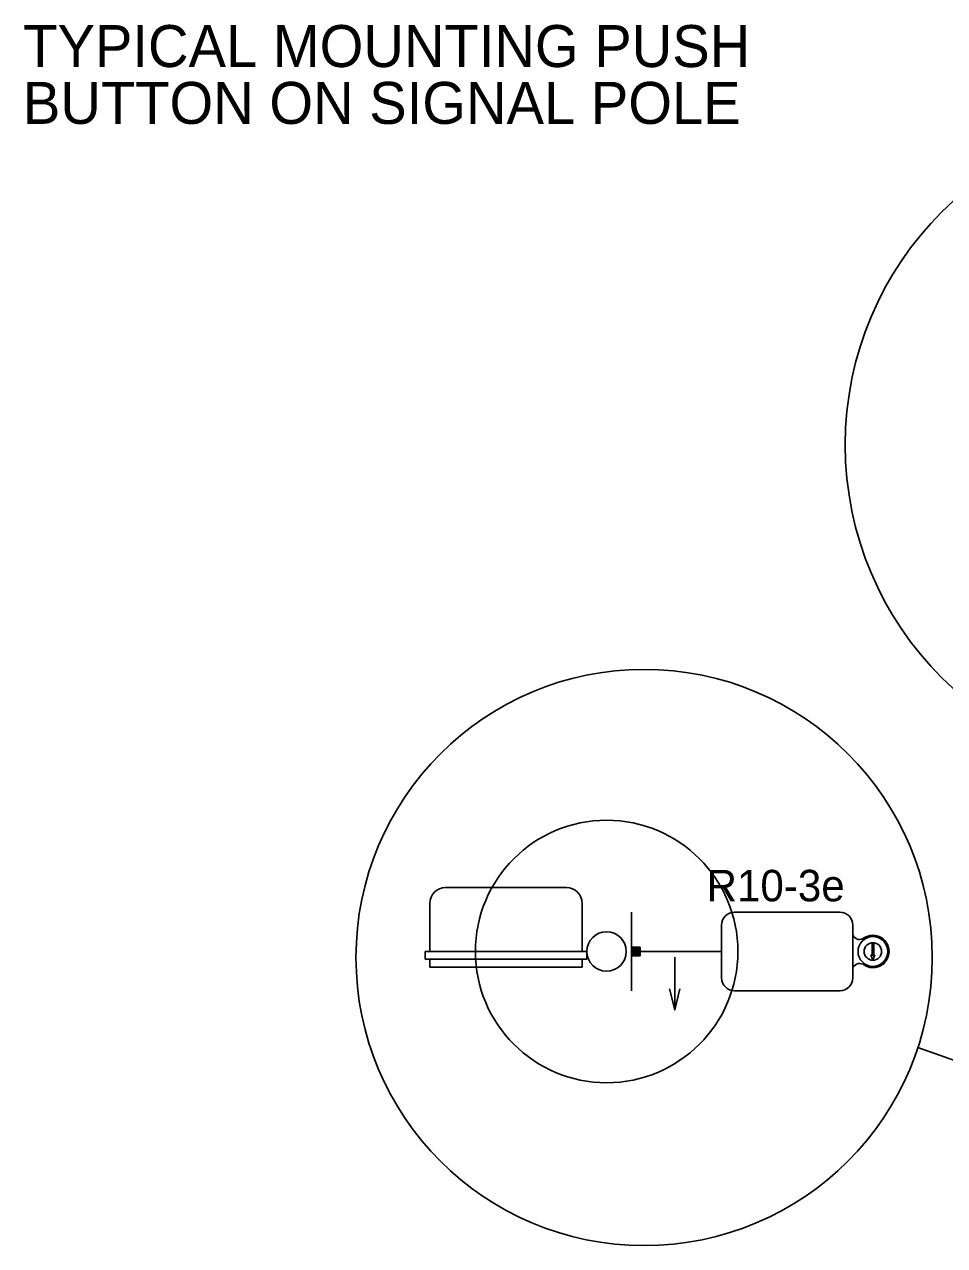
# Model space of a CAD drawing. Extents: x 1695551 to 1695718, y 544410 to 544516.
# Drawn here: x 1695672.78 to 1695694.69, y 544427.73 to 544456.81 of the extents above; entities that cross this region are included whole.
import ezdxf

# ---------------------------------------------------------------- set-up
doc = ezdxf.new("R2010")
doc.units = 0
doc.layers.add('R_Draft', color=7, linetype='Continuous')
doc.layers.add('T_Drafting', color=7, linetype='Continuous')

msp = doc.modelspace()

# ---------------------------------------------------------------- linework, layer by layer
at = {"layer": 'T_Drafting'}
for p, q in [((1695682.808, 544436.257), (1695685.683, 544436.257)), ((1695682.433, 544434.736), (1695682.433, 544435.882)), ((1695686.058, 544434.736), (1695686.058, 544435.882)), ((1695687.235, 544435.674), (1695687.235, 544433.799)), ((1695692.193, 544435.674), (1695689.689, 544435.674)), ((1695689.377, 544435.361), (1695689.377, 544434.111)), ((1695692.506, 544434.111), (1695692.506, 544435.361)), ((1695687.443, 544434.84), (1695687.235, 544434.84)), ((1695687.235, 544434.633), (1695687.442, 544434.84)), ((1695687.235, 544434.636), (1695687.439, 544434.84)), ((1695687.235, 544434.64), (1695687.435, 544434.84)), ((1695687.235, 544434.643), (1695687.432, 544434.84)), ((1695687.235, 544434.647), (1695687.428, 544434.84)), ((1695687.235, 544434.651), (1695687.425, 544434.84)), ((1695687.235, 544434.654), (1695687.421, 544434.84)), ((1695687.235, 544434.658), (1695687.417, 544434.84)), ((1695687.235, 544434.661), (1695687.414, 544434.84)), ((1695687.235, 544434.665), (1695687.41, 544434.84)), ((1695687.235, 544434.668), (1695687.407, 544434.84)), ((1695687.235, 544434.672), (1695687.403, 544434.84)), ((1695687.235, 544434.675), (1695687.4, 544434.84)), ((1695687.235, 544434.679), (1695687.396, 544434.84)), ((1695687.235, 544434.682), (1695687.393, 544434.84)), ((1695687.235, 544434.686), (1695687.389, 544434.84)), ((1695687.235, 544434.689), (1695687.386, 544434.84)), ((1695687.235, 544434.693), (1695687.382, 544434.84)), ((1695687.235, 544434.697), (1695687.379, 544434.84)), ((1695687.235, 544434.7), (1695687.375, 544434.84)), ((1695687.235, 544434.704), (1695687.371, 544434.84)), ((1695687.235, 544434.707), (1695687.368, 544434.84)), ((1695687.235, 544434.711), (1695687.364, 544434.84)), ((1695687.235, 544434.714), (1695687.361, 544434.84)), ((1695687.235, 544434.718), (1695687.357, 544434.84)), ((1695687.235, 544434.721), (1695687.354, 544434.84)), ((1695687.235, 544434.725), (1695687.35, 544434.84)), ((1695687.235, 544434.728), (1695687.347, 544434.84)), ((1695687.235, 544434.732), (1695687.343, 544434.84)), ((1695687.235, 544434.735), (1695687.34, 544434.84)), ((1695687.235, 544434.739), (1695687.336, 544434.84)), ((1695687.235, 544434.742), (1695687.333, 544434.84)), ((1695687.235, 544434.746), (1695687.329, 544434.84)), ((1695687.235, 544434.75), (1695687.326, 544434.84)), ((1695687.235, 544434.753), (1695687.322, 544434.84)), ((1695687.235, 544434.757), (1695687.318, 544434.84)), ((1695687.235, 544434.76), (1695687.315, 544434.84)), ((1695687.235, 544434.764), (1695687.311, 544434.84)), ((1695687.235, 544434.767), (1695687.308, 544434.84)), ((1695687.235, 544434.771), (1695687.304, 544434.84)), ((1695687.235, 544434.774), (1695687.301, 544434.84)), ((1695687.235, 544434.778), (1695687.297, 544434.84)), ((1695687.235, 544434.781), (1695687.294, 544434.84)), ((1695687.235, 544434.785), (1695687.29, 544434.84)), ((1695687.235, 544434.788), (1695687.287, 544434.84)), ((1695687.235, 544434.792), (1695687.283, 544434.84)), ((1695687.235, 544434.796), (1695687.28, 544434.84)), ((1695687.235, 544434.799), (1695687.276, 544434.84)), ((1695687.235, 544434.803), (1695687.272, 544434.84)), ((1695687.235, 544434.806), (1695687.269, 544434.84)), ((1695687.235, 544434.81), (1695687.265, 544434.84)), ((1695687.235, 544434.813), (1695687.262, 544434.84)), ((1695687.235, 544434.817), (1695687.258, 544434.84)), ((1695687.235, 544434.82), (1695687.255, 544434.84)), ((1695687.235, 544434.824), (1695687.251, 544434.84)), ((1695687.235, 544434.827), (1695687.248, 544434.84)), ((1695687.235, 544434.831), (1695687.244, 544434.84)), ((1695687.235, 544434.834), (1695687.241, 544434.84)), ((1695687.235, 544434.838), (1695687.237, 544434.84)), ((1695687.237, 544434.632), (1695687.443, 544434.838)), ((1695687.241, 544434.632), (1695687.443, 544434.834)), ((1695687.244, 544434.632), (1695687.443, 544434.831)), ((1695687.248, 544434.632), (1695687.443, 544434.827)), ((1695687.252, 544434.632), (1695687.443, 544434.824)), ((1695687.255, 544434.632), (1695687.443, 544434.82)), ((1695687.259, 544434.632), (1695687.443, 544434.816)), ((1695687.262, 544434.632), (1695687.443, 544434.813)), ((1695687.266, 544434.632), (1695687.443, 544434.809)), ((1695687.269, 544434.632), (1695687.443, 544434.806)), ((1695687.273, 544434.632), (1695687.443, 544434.802)), ((1695687.443, 544434.632), (1695687.443, 544434.84)), ((1695692.962, 544434.943), (1695693, 544434.943)), ((1695692.962, 544434.629), (1695692.962, 544434.943)), ((1695693, 544434.629), (1695693, 544434.943)), ((1695682.318, 544434.736), (1695686.172, 544434.736)), ((1695682.318, 544434.549), (1695682.318, 544434.736)), ((1695682.318, 544434.549), (1695686.172, 544434.549)), ((1695682.433, 544434.361), (1695682.433, 544434.549)), ((1695686.058, 544434.361), (1695686.058, 544434.549)), ((1695686.172, 544434.549), (1695686.172, 544434.736)), ((1695687.443, 544434.632), (1695687.235, 544434.632)), ((1695687.276, 544434.632), (1695687.443, 544434.799)), ((1695687.28, 544434.632), (1695687.443, 544434.795)), ((1695687.283, 544434.632), (1695687.443, 544434.792)), ((1695687.287, 544434.632), (1695687.443, 544434.788)), ((1695687.29, 544434.632), (1695687.443, 544434.785)), ((1695687.294, 544434.632), (1695687.443, 544434.781)), ((1695687.298, 544434.632), (1695687.443, 544434.778)), ((1695687.301, 544434.632), (1695687.443, 544434.774)), ((1695687.305, 544434.632), (1695687.443, 544434.771)), ((1695687.308, 544434.632), (1695687.443, 544434.767)), ((1695687.312, 544434.632), (1695687.443, 544434.763)), ((1695687.315, 544434.632), (1695687.443, 544434.76)), ((1695687.319, 544434.632), (1695687.443, 544434.756)), ((1695687.322, 544434.632), (1695687.443, 544434.753)), ((1695687.326, 544434.632), (1695687.443, 544434.749)), ((1695687.329, 544434.632), (1695687.443, 544434.746)), ((1695687.333, 544434.632), (1695687.443, 544434.742)), ((1695687.336, 544434.632), (1695687.443, 544434.739)), ((1695687.34, 544434.632), (1695687.443, 544434.735)), ((1695687.343, 544434.632), (1695687.443, 544434.732)), ((1695687.347, 544434.632), (1695687.443, 544434.728)), ((1695687.351, 544434.632), (1695687.443, 544434.725)), ((1695687.354, 544434.632), (1695687.443, 544434.721)), ((1695687.358, 544434.632), (1695687.443, 544434.717)), ((1695687.361, 544434.632), (1695687.443, 544434.714)), ((1695687.365, 544434.632), (1695687.443, 544434.71)), ((1695687.368, 544434.632), (1695687.443, 544434.707)), ((1695687.372, 544434.632), (1695687.443, 544434.703)), ((1695687.375, 544434.632), (1695687.443, 544434.7)), ((1695687.379, 544434.632), (1695687.443, 544434.696)), ((1695687.382, 544434.632), (1695687.443, 544434.693)), ((1695687.386, 544434.632), (1695687.443, 544434.689)), ((1695687.389, 544434.632), (1695687.443, 544434.686)), ((1695687.393, 544434.632), (1695687.443, 544434.682)), ((1695687.397, 544434.632), (1695687.443, 544434.679)), ((1695687.4, 544434.632), (1695687.443, 544434.675)), ((1695687.404, 544434.632), (1695687.443, 544434.672)), ((1695687.407, 544434.632), (1695687.443, 544434.668)), ((1695687.411, 544434.632), (1695687.443, 544434.664)), ((1695687.414, 544434.632), (1695687.443, 544434.661)), ((1695687.418, 544434.632), (1695687.443, 544434.657)), ((1695687.421, 544434.632), (1695687.443, 544434.654)), ((1695687.425, 544434.632), (1695687.443, 544434.65)), ((1695687.428, 544434.632), (1695687.443, 544434.647)), ((1695687.432, 544434.632), (1695687.443, 544434.643)), ((1695687.435, 544434.632), (1695687.443, 544434.64)), ((1695687.439, 544434.632), (1695687.443, 544434.636)), ((1695687.442, 544434.632), (1695687.443, 544434.633)), ((1695687.443, 544434.736), (1695689.377, 544434.736)), ((1695688.262, 544434.603), (1695688.262, 544433.345)), ((1695692.931, 544434.654), (1695692.981, 544434.528)), ((1695692.962, 544434.629), (1695692.931, 544434.654)), ((1695693.031, 544434.654), (1695692.981, 544434.528)), ((1695693.031, 544434.654), (1695693, 544434.629)), ((1695682.433, 544434.361), (1695686.058, 544434.361)), ((1695689.689, 544433.799), (1695692.193, 544433.799)), ((1695697.544, 544431.204), (1695694.052, 544432.449))]:
    msp.add_line(p, q, dxfattribs=at)
msp.add_lwpolyline([(1695688.387, 544433.845), (1695688.262, 544433.345), (1695688.137, 544433.845)], dxfattribs=at)
for centre, radius in [((1695700.16, 544446.801), 7.838), ((1695687.535, 544434.593), 6.861), ((1695686.641, 544434.736), 3.125), ((1695686.641, 544434.736), 0.469), ((1695692.981, 544434.736), 0.354), ((1695692.981, 544434.736), 0.208)]:
    msp.add_circle(centre, radius, dxfattribs=at)
for centre, radius, start, end in [((1695682.808, 544435.882), 0.375, 90, 180), ((1695685.683, 544435.882), 0.375, 360, 90), ((1695689.689, 544435.361), 0.312, 90, 180), ((1695692.193, 544435.361), 0.312, 0, 90), ((1695692.664, 544435.196), 0.175, 205.1956, 311.8028), ((1695692.981, 544434.736), 0.385, 238.7402, 121.2598), ((1695692.981, 544434.736), 0.385, 42.5066, 121.2598), ((1695692.664, 544434.276), 0.175, 48.1972, 154.8044), ((1695692.981, 544434.736), 0.385, 238.7402, 317.4934), ((1695689.689, 544434.111), 0.312, 180, 270), ((1695692.193, 544434.111), 0.312, 270, 0)]:
    msp.add_arc(centre, radius, start, end, dxfattribs=at)

# ---------------------------------------------------------------- texts
at = {"layer": 'R_Draft'}
for s, p in [('TYPICAL MOUNTING PUSH ', (1695672.75, 544455.798)), ('BUTTON ON SIGNAL POLE ', (1695672.743, 544454.444))]:
    msp.add_text(s, height=1, dxfattribs=at).set_placement(p)
at = {"layer": 'T_Drafting'}
msp.add_text('R10-3e', height=0.75, dxfattribs=at).set_placement((1695689.021, 544435.93))

doc.saveas('drawing.dxf')
